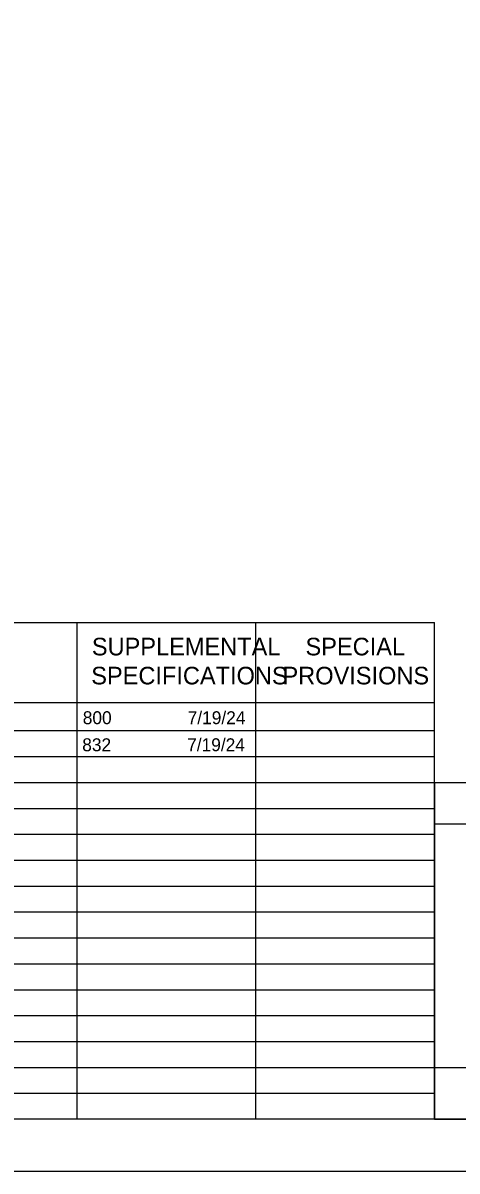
# Model space of a CAD drawing. Extents: x 0 to 34, y 0 to 22.
# Drawn here: x 19.63 to 23.82, y 0 to 11.08 of the extents above; entities that cross this region are included whole.
import ezdxf

# ---------------------------------------------------------------- set-up
doc = ezdxf.new("R2010")
doc.units = 0
for name, color, linetype in [('SH_Border', 7, 'Continuous'), ('SH_Cut_Line', 7, 'Continuous'), ('SH_Data', 7, 'Continuous'), ('SH_Text', 7, 'Continuous')]:
    doc.layers.add(name, color=color, linetype=linetype)

msp = doc.modelspace()

# ---------------------------------------------------------------- linework, layer by layer
at = {"layer": 'SH_Border'}
msp.add_lwpolyline([(1.5, 21.5), (33.5, 21.5), (33.5, 0.5), (1.5, 0.5)], close=True, dxfattribs=at)
at = {"layer": 'SH_Cut_Line'}
msp.add_lwpolyline([(0, 0), (34, 0), (34, 22), (0, 22)], close=True, dxfattribs=at)
at = {"layer": 'SH_Data'}
for p, q in [((10.15, 5.292), (23.6, 5.292)), ((20.15, 0.5), (20.15, 5.292)), ((21.875, 0.5), (21.875, 5.292)), ((23.6, 0.5), (23.6, 5.292)), ((10.15, 4.521), (23.6, 4.521)), ((10.15, 4.25), (23.6, 4.25)), ((10.15, 4), (23.6, 4)), ((10.15, 3.75), (23.6, 3.75)), ((23.6, 0.5), (23.6, 3.75)), ((23.6, 3.75), (23.6, 0.5)), ((23.6, 0.5), (23.6, 3.75)), ((23.6, 3.75), (26.4, 3.75)), ((10.15, 3.5), (23.6, 3.5)), ((23.6, 3.35), (26.4, 3.35)), ((10.15, 3.25), (23.6, 3.25)), ((10.15, 3), (23.6, 3)), ((10.15, 2.75), (23.6, 2.75)), ((10.15, 2.5), (23.6, 2.5)), ((10.15, 2.25), (23.6, 2.25)), ((10.15, 2), (23.6, 2)), ((10.15, 1.75), (23.6, 1.75)), ((10.15, 1.5), (23.6, 1.5)), ((10.15, 1.25), (23.6, 1.25)), ((10.15, 1), (23.6, 1)), ((10.15, 0.75), (23.6, 0.75)), ((23.6, 0.5), (26.4, 0.5))]:
    msp.add_line(p, q, dxfattribs=at)
msp.add_lwpolyline([(23.6, 0.5), (23.6, 1), (26.4, 1), (26.4, 0.5)], close=True, dxfattribs=at)

# ---------------------------------------------------------------- texts
for s, p in [('800', (20.205, 4.312)), ('7/19/24', (21.217, 4.312)), ('832', (20.2, 4.051)), ('7/19/24', (21.212, 4.051))]:
    msp.add_text(s, height=0.125, dxfattribs=at).set_placement(p)
at = {"layer": 'SH_Text'}
for s, p in [('SUPPLEMENTAL', (20.293, 4.976)), ('SPECIAL', (22.354, 4.976)), ('SPECIFICATIONS', (20.287, 4.696)), ('PROVISIONS', (22.132, 4.696))]:
    msp.add_text(s, height=0.17, dxfattribs=at).set_placement(p)

doc.saveas('drawing.dxf')
